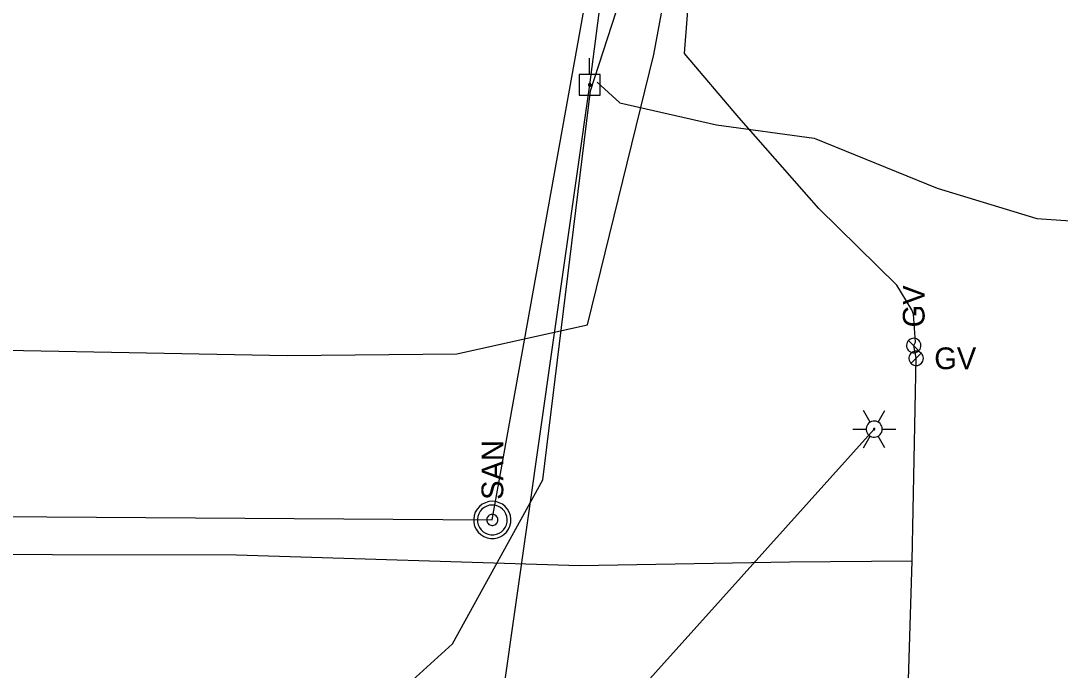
# Model space of a CAD drawing. Extents: x 600849 to 606371, y 330010 to 403088.
# Drawn here: x 601694.1 to 601878.2, y 355528.5 to 355643.5 of the extents above; entities that cross this region are included whole.
import ezdxf

# ---------------------------------------------------------------- set-up
doc = ezdxf.new("R2010")
doc.units = 0
for name, color, linetype in [('E_LTG', 7, 'Continuous'), ('E_UTL_EPowerPole', 7, 'Continuous'), ('E_UTL_FO_UG_MWFN', 7, 'Continuous'), ('E_UTL_G', 7, 'Continuous'), ('E_UTL_G_UG', 7, 'Continuous'), ('E_UTL_Overhead', 7, 'Continuous'), ('E_UTL_SAN', 7, 'Continuous'), ('E_UTL_SAN_UG', 7, 'Continuous'), ('E_UTL_T_UG', 7, 'Continuous')]:
    doc.layers.add(name, color=color, linetype=linetype)

msp = doc.modelspace()

# ---------------------------------------------------------------- linework, layer by layer
at = {"layer": 'E_LTG'}
for points in [[(601844.53, 355572.43), (601843.34, 355574.5)], [(601845.96, 355572.43), (601847.15, 355574.5)], [(601846.68, 355571.2), (601846.65, 355571.47), (601846.57, 355571.73), (601846.45, 355571.97), (601846.28, 355572.18), (601846.08, 355572.36), (601845.84, 355572.5), (601845.59, 355572.58), (601845.32, 355572.62), (601845.04, 355572.61), (601844.78, 355572.55), (601844.53, 355572.43), (601844.31, 355572.28), (601844.13, 355572.08), (601843.98, 355571.85), (601843.88, 355571.6), (601843.83, 355571.33), (601843.83, 355571.06), (601843.88, 355570.79), (601843.98, 355570.54), (601844.13, 355570.31), (601844.31, 355570.12), (601844.53, 355569.96), (601844.78, 355569.85), (601845.04, 355569.78), (601845.32, 355569.77), (601845.59, 355569.81), (601845.84, 355569.9), (601846.08, 355570.03), (601846.28, 355570.21), (601846.45, 355570.42), (601846.57, 355570.66), (601846.65, 355570.93), (601846.68, 355571.2)], [(601846.68, 355571.2), (601846.65, 355571.47), (601846.57, 355571.73), (601846.45, 355571.97), (601846.28, 355572.18), (601846.08, 355572.36), (601845.84, 355572.5), (601845.59, 355572.58), (601845.32, 355572.62), (601845.04, 355572.61), (601844.78, 355572.55), (601844.53, 355572.43), (601844.31, 355572.28), (601844.13, 355572.08), (601843.98, 355571.85), (601843.88, 355571.6), (601843.83, 355571.33), (601843.83, 355571.06), (601843.88, 355570.79), (601843.98, 355570.54), (601844.13, 355570.31), (601844.31, 355570.12), (601844.53, 355569.96), (601844.78, 355569.85), (601845.04, 355569.78), (601845.32, 355569.77), (601845.59, 355569.81), (601845.84, 355569.9), (601846.08, 355570.03), (601846.28, 355570.21), (601846.45, 355570.42), (601846.57, 355570.66), (601846.65, 355570.93), (601846.68, 355571.2)], [(601846.68, 355571.2), (601846.65, 355571.47), (601846.57, 355571.73), (601846.45, 355571.97), (601846.28, 355572.18), (601846.08, 355572.36), (601845.84, 355572.5), (601845.59, 355572.58), (601845.32, 355572.62), (601845.04, 355572.61), (601844.78, 355572.55), (601844.53, 355572.43), (601844.31, 355572.28), (601844.13, 355572.08), (601843.98, 355571.85), (601843.88, 355571.6), (601843.83, 355571.33), (601843.83, 355571.06), (601843.88, 355570.79), (601843.98, 355570.54), (601844.13, 355570.31), (601844.31, 355570.12), (601844.53, 355569.96), (601844.78, 355569.85), (601845.04, 355569.78), (601845.32, 355569.77), (601845.59, 355569.81), (601845.84, 355569.9), (601846.08, 355570.03), (601846.28, 355570.21), (601846.45, 355570.42), (601846.57, 355570.66), (601846.65, 355570.93), (601846.68, 355571.2)], [(601841.44, 355571.2), (601843.82, 355571.2)], [(601845.37, 355571.2), (601845.37, 355571.22), (601845.36, 355571.24), (601845.35, 355571.26), (601845.33, 355571.28), (601845.32, 355571.29), (601845.3, 355571.3), (601845.28, 355571.31), (601845.25, 355571.31), (601845.23, 355571.31), (601845.21, 355571.31), (601845.19, 355571.3), (601845.17, 355571.29), (601845.15, 355571.27), (601845.14, 355571.25), (601845.13, 355571.23), (601845.13, 355571.21), (601845.13, 355571.18), (601845.13, 355571.16), (601845.14, 355571.14), (601845.15, 355571.12), (601845.17, 355571.11), (601845.19, 355571.09), (601845.21, 355571.08), (601845.23, 355571.08), (601845.25, 355571.08), (601845.28, 355571.08), (601845.3, 355571.09), (601845.32, 355571.1), (601845.33, 355571.11), (601845.35, 355571.13), (601845.36, 355571.15), (601845.37, 355571.17), (601845.37, 355571.2)], [(601846.68, 355571.2), (601849.06, 355571.2)], [(601843.34, 355567.9), (601844.53, 355569.96)], [(601847.15, 355567.9), (601845.96, 355569.96)]]:
    msp.add_lwpolyline(points, dxfattribs=at)
at = {"layer": 'E_UTL_EPowerPole'}
for points in [[(601794.84, 355633.98), (601794.84, 355636.89)], [(601796.69, 355633.98), (601793, 355633.98)], [(601793, 355633.98), (601793, 355630.29)], [(601796.69, 355630.29), (601796.69, 355633.98)], [(601795.11, 355632.14), (601795.11, 355632.18), (601795.1, 355632.23), (601795.08, 355632.27), (601795.05, 355632.3), (601795.01, 355632.33), (601794.98, 355632.36), (601794.93, 355632.37), (601794.89, 355632.38), (601794.84, 355632.37), (601794.8, 355632.36), (601794.76, 355632.35), (601794.72, 355632.32), (601794.69, 355632.29), (601794.66, 355632.25), (601794.65, 355632.21), (601794.64, 355632.16), (601794.64, 355632.12), (601794.65, 355632.07), (601794.66, 355632.03), (601794.69, 355631.99), (601794.72, 355631.96), (601794.76, 355631.93), (601794.8, 355631.91), (601794.84, 355631.9), (601794.89, 355631.9), (601794.93, 355631.91), (601794.98, 355631.92), (601795.01, 355631.94), (601795.05, 355631.97), (601795.08, 355632.01), (601795.1, 355632.05), (601795.11, 355632.09), (601795.11, 355632.14)], [(601793, 355630.29), (601796.69, 355630.29)]]:
    msp.add_lwpolyline(points, dxfattribs=at)
at = {"layer": 'E_UTL_FO_UG_MWFN'}
msp.add_lwpolyline([(601796.2, 355632.59), (601800.17, 355628.96), (601817.29, 355625.05), (601834.59, 355622.69), (601856.42, 355613.87), (601874.03, 355608.46), (601891.12, 355607.3), (601910.08, 355608.77), (601952.11, 355610.04), (601973.02, 355612.38), (602011.95, 355614.57), (602029.82, 355616.96), (602046.83, 355617.69), (602063.23, 355617.42), (602101.87, 355619.2), (602132, 355621.3), (602192.86, 355609.41), (602217.67, 355614.05), (602225.6, 355618.4), (602230.48, 355623.17), (602232.65, 355626.78), (602235.2, 355621.54), (602234.9, 355612.22), (602235.64, 355572.37)], dxfattribs=at)
at = {"layer": 'E_UTL_G'}
for points in [[(601852.25, 355587.28), (601852, 355587.25), (601851.77, 355587.18), (601851.55, 355587.07), (601851.36, 355586.92), (601851.2, 355586.74), (601851.08, 355586.52), (601851, 355586.29), (601850.96, 355586.05), (601850.98, 355585.81), (601851.03, 355585.57), (601851.13, 355585.35), (601851.28, 355585.15), (601851.45, 355584.98), (601851.66, 355584.85), (601851.88, 355584.76), (601852.12, 355584.71), (601852.37, 355584.71), (601852.61, 355584.76), (601852.83, 355584.85), (601853.04, 355584.98), (601853.22, 355585.15), (601853.36, 355585.35), (601853.46, 355585.57), (601853.52, 355585.81), (601853.53, 355586.05), (601853.49, 355586.29), (601853.41, 355586.52), (601853.29, 355586.74), (601853.13, 355586.92), (601852.94, 355587.07), (601852.72, 355587.18), (601852.49, 355587.25), (601852.25, 355587.28)], [(601853.15, 355585.08), (601851.34, 355586.9)], [(601853.95, 355583.73), (601853.93, 355583.97), (601853.86, 355584.2), (601853.75, 355584.42), (601853.6, 355584.61), (601853.41, 355584.77), (601853.2, 355584.9), (601852.97, 355584.97), (601852.73, 355585.01), (601852.49, 355585), (601852.25, 355584.94), (601852.03, 355584.84), (601851.83, 355584.7), (601851.66, 355584.52), (601851.53, 355584.32), (601851.44, 355584.09), (601851.39, 355583.85), (601851.39, 355583.61), (601851.44, 355583.37), (601851.53, 355583.14), (601851.66, 355582.93), (601851.83, 355582.76), (601852.03, 355582.62), (601852.25, 355582.52), (601852.49, 355582.46), (601852.73, 355582.45), (601852.97, 355582.48), (601853.2, 355582.56), (601853.41, 355582.68), (601853.6, 355582.84), (601853.75, 355583.03), (601853.86, 355583.25), (601853.93, 355583.48), (601853.95, 355583.73)], [(601851.76, 355582.82), (601853.58, 355584.64)]]:
    msp.add_lwpolyline(points, dxfattribs=at)
at = {"layer": 'E_UTL_G_UG'}
for points in [[(601497.89, 355586.04), (601557.2, 355585.04), (601608.23, 355585.72), (601666.55, 355585.63), (601741.3, 355584.2), (601771.33, 355584.5), (601794.45, 355589.66), (601806.2, 355637.49), (601811.35, 355665.27), (601815.89, 355691.42), (601823.98, 355737.46), (601828.35, 355766.99)], [(601849.27, 355302.12), (601850.99, 355344.89), (601850.21, 355393.81), (601851.15, 355473.2), (601850.21, 355490.44), (601851.95, 355547.88), (601852.67, 355583.73), (601852.25, 355585.99), (601852.56, 355586.58), (601852.19, 355591.55), (601851.91, 355592.32), (601849.25, 355596.66), (601835.45, 355610.23), (601821.29, 355626.35), (601811.64, 355637.69), (601814.09, 355668.92), (601823.14, 355722.3), (601823.37, 355723.2), (601828.74, 355757.82), (601829.7, 355765.72)], [(601281.11, 355548.99), (601456.8, 355548.88), (601501.85, 355546.55), (601540.47, 355547.26), (601567.93, 355547.51), (601604.28, 355548.55), (601619.98, 355548.78), (601633.71, 355549.19), (601652.23, 355549.07), (601667.06, 355549.06), (601732.27, 355548.91), (601793.04, 355547.03), (601830.3, 355547.67), (601851.95, 355547.88)]]:
    msp.add_lwpolyline(points, dxfattribs=at)
at = {"layer": 'E_UTL_Overhead'}
for points in [[(601775.11, 355493.17), (601794.88, 355632.14), (601813.19, 355774.43), (601846.41, 355956.03), (601876.1, 356114.7), (601902.03, 356254.58), (601928.02, 356393.42), (601947.92, 356557.45), (601949.4, 356721.2), (601951.31, 356874.93), (601952.99, 357026.21), (601955.32, 357157.12), (601956.05, 357297.31), (601956.02, 357419.23)], [(601775.11, 355493.17), (601845.25, 355571.2)]]:
    msp.add_lwpolyline(points, dxfattribs=at)
at = {"layer": 'E_UTL_SAN'}
for points in [[(601777.6, 355558.41), (601776.98, 355558.35), (601776.38, 355558.17), (601775.82, 355557.88), (601775.33, 355557.5), (601774.91, 355557.02), (601774.6, 355556.48), (601774.4, 355555.89), (601774.31, 355555.26), (601774.34, 355554.64), (601774.48, 355554.03), (601774.74, 355553.46), (601775.11, 355552.95), (601775.56, 355552.51), (601776.09, 355552.17), (601776.67, 355551.94), (601777.29, 355551.82), (601777.92, 355551.82), (601778.53, 355551.94), (601779.11, 355552.17), (601779.64, 355552.51), (601780.1, 355552.95), (601780.46, 355553.46), (601780.72, 355554.03), (601780.87, 355554.64), (601780.9, 355555.26), (601780.81, 355555.89), (601780.6, 355556.48), (601780.29, 355557.02), (601779.88, 355557.5), (601779.39, 355557.88), (601778.83, 355558.17), (601778.23, 355558.35), (601777.6, 355558.41)], [(601777.6, 355557.75), (601777.1, 355557.7), (601776.62, 355557.56), (601776.18, 355557.33), (601775.78, 355557.02), (601775.45, 355556.64), (601775.2, 355556.2), (601775.04, 355555.73), (601774.97, 355555.23), (601774.99, 355554.73), (601775.11, 355554.24), (601775.32, 355553.79), (601775.61, 355553.38), (601775.97, 355553.03), (601776.39, 355552.76), (601776.86, 355552.57), (601777.35, 355552.48), (601777.85, 355552.48), (601778.35, 355552.57), (601778.81, 355552.76), (601779.23, 355553.03), (601779.6, 355553.38), (601779.89, 355553.79), (601780.1, 355554.24), (601780.22, 355554.73), (601780.24, 355555.23), (601780.17, 355555.73), (601780, 355556.2), (601779.75, 355556.64), (601779.42, 355557.02), (601779.03, 355557.33), (601778.58, 355557.56), (601778.1, 355557.7), (601777.6, 355557.75)], [(601777.6, 355556.1), (601777.41, 355556.08), (601777.23, 355556.03), (601777.07, 355555.94), (601776.92, 355555.82), (601776.8, 355555.68), (601776.7, 355555.52), (601776.64, 355555.34), (601776.61, 355555.15), (601776.62, 355554.97), (601776.67, 355554.78), (601776.74, 355554.61), (601776.85, 355554.46), (601776.99, 355554.33), (601777.15, 355554.23), (601777.32, 355554.16), (601777.51, 355554.12), (601777.7, 355554.12), (601777.88, 355554.16), (601778.06, 355554.23), (601778.21, 355554.33), (601778.35, 355554.46), (601778.46, 355554.61), (601778.54, 355554.78), (601778.58, 355554.97), (601778.59, 355555.15), (601778.56, 355555.34), (601778.5, 355555.52), (601778.41, 355555.68), (601778.29, 355555.82), (601778.14, 355555.94), (601777.97, 355556.03), (601777.79, 355556.08), (601777.6, 355556.1)]]:
    msp.add_lwpolyline(points, dxfattribs=at)
at = {"layer": 'E_UTL_SAN_UG'}
for p, q in [((601777.6, 355555.11), (601825.37, 355821.01)), ((601442.88, 355557.35), (601777.6, 355555.11))]:
    msp.add_line(p, q, dxfattribs=at)
at = {"layer": 'E_UTL_T_UG'}
msp.add_lwpolyline([(601555.15, 355293.25), (601546.07, 355328.55), (601537.79, 355381.85), (601535.72, 355429.97), (601535.59, 355468.25), (601535.1, 355479.19), (601535.6, 355482.46), (601543.19, 355485.84), (601553.05, 355488.3), (601593.31, 355492.85), (601624.11, 355494.98), (601694.31, 355491.72), (601734.08, 355499.88), (601743.92, 355509.01), (601770.57, 355533.15), (601786.55, 355562.19), (601794.99, 355631.11), (601804.92, 355661.67), (601832.53, 355819.68), (601858.24, 355964.25), (601877.3, 356057.56)], dxfattribs=at)

# ---------------------------------------------------------------- texts
at = {"layer": 'E_UTL_G'}
msp.add_text('GV', height=3.85, rotation=90, dxfattribs=at).set_placement((601854.17, 355589.2))
msp.add_text('GV', height=3.85, dxfattribs=at).set_placement((601855.88, 355581.8))
at = {"layer": 'E_UTL_SAN'}
msp.add_text('SAN', height=3.849, rotation=90, dxfattribs=at).set_placement((601779.55, 355558.67))

doc.saveas('drawing.dxf')
